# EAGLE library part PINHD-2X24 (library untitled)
PIN HEADER
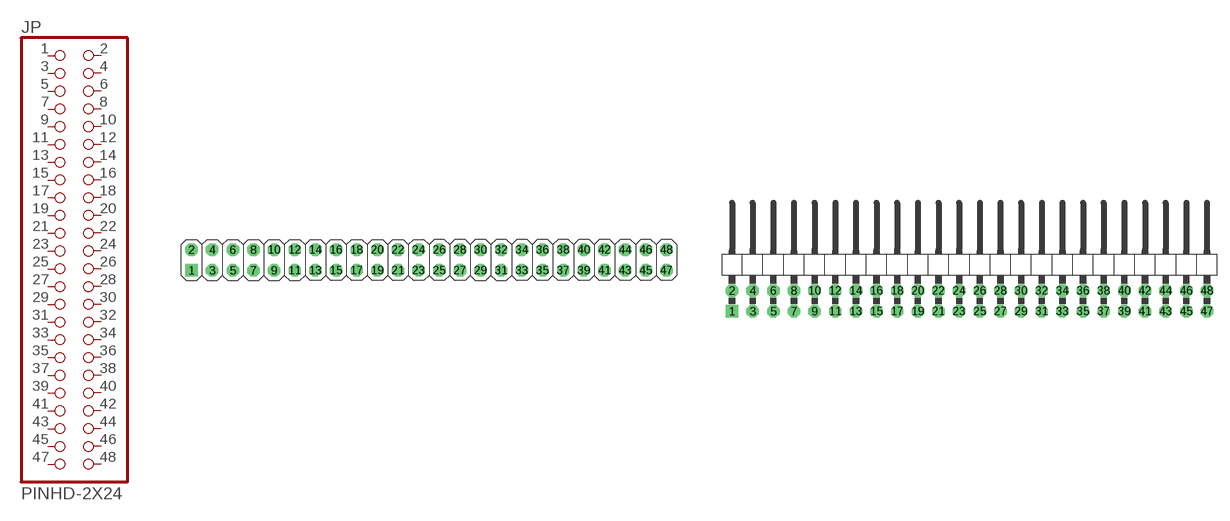
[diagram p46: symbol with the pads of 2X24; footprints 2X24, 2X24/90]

Designator prefix JP

## PINHD-2X24_2.54  [2X24]
1  1  pas
2  2  pas
3  3  pas
4  4  pas
5  5  pas
6  6  pas
7  7  pas
8  8  pas
9  9  pas
10  10  pas
11  11  pas
12  12  pas
13  13  pas
14  14  pas
15  15  pas
16  16  pas
17  17  pas
18  18  pas
19  19  pas
20  20  pas
21  21  pas
22  22  pas
23  23  pas
24  24  pas
25  25  pas
26  26  pas
27  27  pas
28  28  pas
29  29  pas
30  30  pas
31  31  pas
32  32  pas
33  33  pas
34  34  pas
35  35  pas
36  36  pas
37  37  pas
38  38  pas
39  39  pas
40  40  pas
41  41  pas
42  42  pas
43  43  pas
44  44  pas
45  45  pas
46  46  pas
47  47  pas
48  48  pas

## PINHD-2X24_2.54-90°  [2X24/90]
Pads as for 2X24

## PINHD-2X24_2.00  [2X24M]
Pads as for 2X24

## PINHD-2X24_2.54-SMD  [2X24SMD]
Pads as for 2X24

## PINHD-2X24_2.54-SMD-90°  [2X24SMD/90]
Pads as for 2X24

## Footprint 2X24 (pad centres in mm)
PIN HEADER - 2.54
drill 1.016 square: 1 -27.94,-1.27
drill 1.016 octagon: 2 -27.94,1.27; 3 -25.4,-1.27; 4 -25.4,1.27; 5 -22.86,-1.27; 6 -22.86,1.27; 7 -20.32,-1.27; 8 -20.32,1.27; 9 -17.78,-1.27; 10 -17.78,1.27; 11 -15.24,-1.27; 12 -15.24,1.27; 13 -12.7,-1.27; 14 -12.7,1.27; 15 -10.16,-1.27; 16 -10.16,1.27; 17 -7.62,-1.27; 18 -7.62,1.27; 19 -5.08,-1.27; 20 -5.08,1.27; 21 -2.54,-1.27; 22 -2.54,1.27; 23 0,-1.27; 24 0,1.27; 25 2.54,-1.27; 26 2.54,1.27; 27 5.08,-1.27; 28 5.08,1.27; 29 7.62,-1.27; 30 7.62,1.27; 31 10.16,-1.27; 32 10.16,1.27; 33 12.7,-1.27; 34 12.7,1.27; 35 15.24,-1.27; 36 15.24,1.27; 37 17.78,-1.27; 38 17.78,1.27; 39 20.32,-1.27; 40 20.32,1.27; 41 22.86,-1.27; 42 22.86,1.27; 43 25.4,-1.27; 44 25.4,1.27; 45 27.94,-1.27; 46 27.94,1.27; 47 30.48,-1.27; 48 30.48,1.27

## Footprint 2X24/90 (pad centres in mm)
PIN HEADER - 2.54 90°
drill 1.016 square: 1 -24.13,-6.35
drill 1.016 octagon: 2 -24.13,-3.81; 3 -21.59,-6.35; 4 -21.59,-3.81; 5 -19.05,-6.35; 6 -19.05,-3.81; 7 -16.51,-6.35; 8 -16.51,-3.81; 9 -13.97,-6.35; 10 -13.97,-3.81; 11 -11.43,-6.35; 12 -11.43,-3.81; 13 -8.89,-6.35; 14 -8.89,-3.81; 15 -6.35,-6.35; 16 -6.35,-3.81; 17 -3.81,-6.35; 18 -3.81,-3.81; 19 -1.27,-6.35; 20 -1.27,-3.81; 21 1.27,-6.35; 22 1.27,-3.81; 23 3.81,-6.35; 24 3.81,-3.81; 25 6.35,-6.35; 26 6.35,-3.81; 27 8.89,-6.35; 28 8.89,-3.81; 29 11.43,-6.35; 30 11.43,-3.81; 31 13.97,-6.35; 32 13.97,-3.81; 33 16.51,-6.35; 34 16.51,-3.81; 35 19.05,-6.35; 36 19.05,-3.81; 37 21.59,-6.35; 38 21.59,-3.81; 39 24.13,-6.35; 40 24.13,-3.81; 41 26.67,-6.35; 42 26.67,-3.81; 43 29.21,-6.35; 44 29.21,-3.81; 45 31.75,-6.35; 46 31.75,-3.81; 47 34.29,-6.35; 48 34.29,-3.81

## Footprint 2X24M (pad centres in mm)
PIN HEADER - 2
drill 0.914 square: 1 -23,-1
drill 0.914 round: 2 -23,1; 3 -21,-1; 4 -21,1; 5 -19,-1; 6 -19,1; 7 -17,-1; 8 -17,1; 9 -15,-1; 10 -15,1; 11 -13,-1; 12 -13,1; 13 -11,-1; 14 -11,1; 15 -9,-1; 16 -9,1; 17 -7,-1; 18 -7,1; 19 -5,-1; 20 -5,1; 21 -3,-1; 22 -3,1; 23 -1,-1; 24 -1,1; 25 1,-1; 26 1,1; 27 3,-1; 28 3,1; 29 5,-1; 30 5,1; 31 7,-1; 32 7,1; 33 9,-1; 34 9,1; 35 11,-1; 36 11,1; 37 13,-1; 38 13,1; 39 15,-1; 40 15,1; 41 17,-1; 42 17,1; 43 19,-1; 44 19,1; 45 21,-1; 46 21,1; 47 23,-1; 48 23,1

## Footprint 2X24SMD (pad centres in mm)
PIN HEADER - 2.54 SMD
smd 1.016 x 3.302: 1 -1.27,-3.81; 2 -1.27,1.27; 3 1.27,-3.81; 4 1.27,1.27; 5 3.81,-3.81; 6 3.81,1.27; 7 6.35,-3.81; 8 6.35,1.27; 9 8.89,-3.81; 10 8.89,1.27; 11 11.43,-3.81; 12 11.43,1.27; 13 13.97,-3.81; 14 13.97,1.27; 15 16.51,-3.81; 16 16.51,1.27; 17 19.05,-3.81; 18 19.05,1.27; 19 21.59,-3.81; 20 21.59,1.27; 21 24.13,-3.81; 22 24.13,1.27; 23 26.67,-3.81; 24 26.67,1.27; 25 29.21,-3.81; 26 29.21,1.27; 27 31.75,-3.81; 28 31.75,1.27; 29 34.29,-3.81; 30 34.29,1.27; 31 36.83,-3.81; 32 36.83,1.27; 33 39.37,-3.81; 34 39.37,1.27; 35 41.91,-3.81; 36 41.91,1.27; 37 44.45,-3.81; 38 44.45,1.27; 39 46.99,-3.81; 40 46.99,1.27; 41 49.53,-3.81; 42 49.53,1.27; 43 52.07,-3.81; 44 52.07,1.27; 45 54.61,-3.81; 46 54.61,1.27; 47 57.15,-3.81; 48 57.15,1.27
